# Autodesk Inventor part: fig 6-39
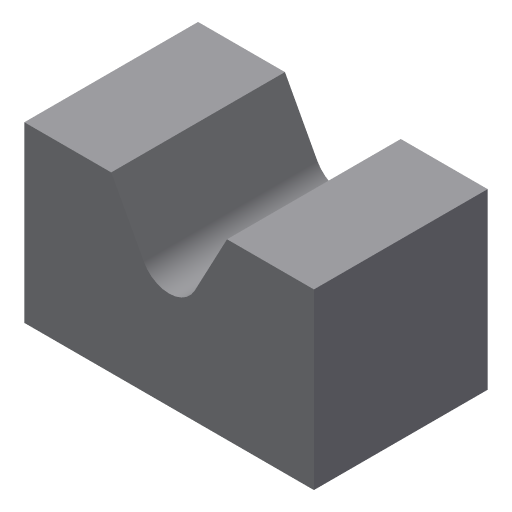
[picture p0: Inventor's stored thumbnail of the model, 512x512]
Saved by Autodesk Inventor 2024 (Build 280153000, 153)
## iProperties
Created: 2005-12
Part Number: fig 6-39
Document SubType Name: Modeling
Designer: CADCIM
Density: 1 g/cm^3
Material: Generic
Appearance: Default
Author: CADCIM
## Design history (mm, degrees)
sketch "Sketch1"
  geometry: L1 (10, 15)-(25, 15); L2 (25, 15)-(25, -15); L3 (25, -15)-(-25, -15); L4 (-25, -15)-(-25, 15); L5 (-25, 15)-(-10, 15); L6 (-10, 15)-(-2, 0); L7 (-2, 0)-(2, 0); L8 (2, 0)-(10, 15); 1 further point
  constraints: 16 end point, 3 equal length, 3 parallel, 1 collinear, 1 horizontal, 1 perpendicular, 1 other
  dimensions: "d0" = 50 distance of L2.end L3.end; "d1" = 25 distance from line of point (0, 0) L2; "d2" = 30 distance of L1.end L2.end; "d3" = 15 distance of L1.start L1.end; "d4" = 15 distance between parallel lines of L1 L7; "d5" = 4 distance of L6.end L7.end; "d6" = 15 distance from line of point (0, 0) L3
extrude "Extrusion1" new body sketch "Sketch1" stored distance "d7" = 30; taper "d8" = 0 deg
fillet "Fillet4" dims "d11" = 5
body "Solid1"
